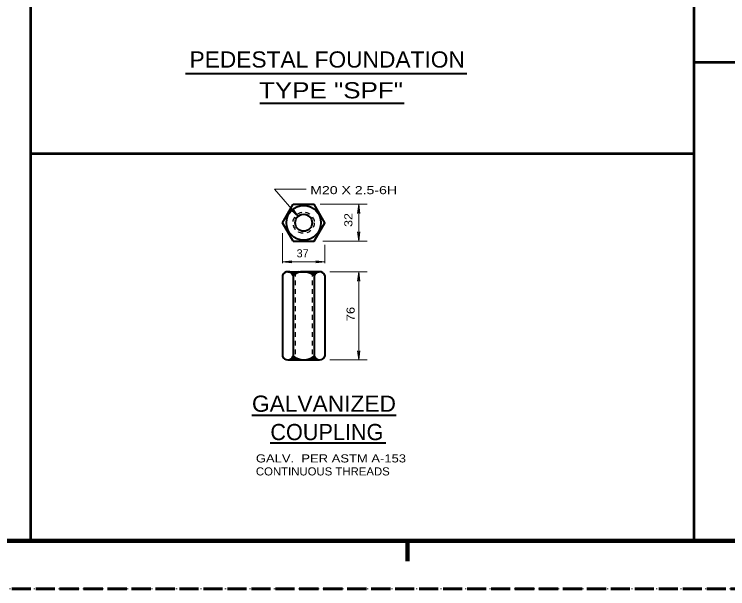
# Model space of a CAD drawing. Extents: x 312583 to 312854, y 144419 to 144597.
# Drawn here: x 312690.4 to 312757.4, y 144418.6 to 144472.5 of the extents above; entities that cross this region are included whole.
import ezdxf
from ezdxf.enums import TextEntityAlignment as Align

# ---------------------------------------------------------------- set-up
doc = ezdxf.new("R2010")
doc.units = 0
doc.header["$LTSCALE"] = 0.3
for name, pattern in [('DOTTED', [1.5, 0.3, -1.2]), ('LONG_DASHED', [7.5, 6, -1.5]), ('SHORT_DASHED', [2.7, 1.5, -1.2])]:
    doc.linetypes.add(name, pattern=pattern)
for name, color, linetype, lineweight in [('1', 7, 'Continuous', 25), ('2', 7, 'Continuous', 13), ('62', 7, 'DOTTED', 13), ('63', 7, 'LONG_DASHED', 60)]:
    doc.layers.add(name, color=color, linetype=linetype, lineweight=lineweight)

msp = doc.modelspace()

# ---------------------------------------------------------------- linework, layer by layer
at = {"layer": '1', "lineweight": 53}
for p, q in [((312691.9772, 144423.0846), (312691.9772, 144585.0846)), ((312754.2862, 144423.0846), (312754.2862, 144585.0846)), ((312849, 144468), (312754.2862, 144468)), ((312754.2862, 144459.4229), (312691.9772, 144459.4229))]:
    msp.add_line(p, q, dxfattribs=at)
at = {"layer": '1', "lineweight": 40}
for p, q in [((312715.6179, 144452.9535), (312716.6145, 144454.6785)), ((312716.6145, 144454.6785), (312718.6079, 144454.6785)), ((312716.6145, 144451.2285), (312715.6179, 144452.9535)), ((312716.6145, 144451.2285), (312718.6079, 144451.2285)), ((312715.6179, 144448.0009), (312715.6179, 144440.4109)), ((312716.1162, 144448.3459), (312719.0602, 144448.3459)), ((312716.6145, 144448.0009), (312716.6145, 144440.4109)), ((312718.6002, 144448.0009), (312718.6002, 144440.4109)), ((312719.6045, 144448.0009), (312719.6045, 144440.4109)), ((312716.1162, 144440.0659), (312719.0602, 144440.0659)), ((312716.1162, 144440.0659), (312719.0602, 144440.0659))]:
    msp.add_line(p, q, dxfattribs=at)
at = {"layer": '1', "linetype": 'SHORT_DASHED'}
for p, q in [((312716.8139, 144448.3459), (312716.8139, 144440.0659)), ((312718.4085, 144448.3459), (312718.4085, 144440.0659))]:
    msp.add_line(p, q, dxfattribs=at)
at = {"layer": '1', "lineweight": 158}
for p, q in [((312616.5, 144423.0846), (312849, 144423.0846)), ((312727.35, 144421.1646), (312727.35, 144423.0846))]:
    msp.add_line(p, q, dxfattribs=at)
at = {"layer": '1', "lineweight": 40}
for points in [[(312718.6079, 144451.2285), (312719.6045, 144452.9535), (312718.6079, 144454.6785)], [(312716.2695, 144448.3382), (312717.3429, 144448.3459), (312717.1205, 144448.2922), (312716.8675, 144448.1849), (312716.6375, 144448.0315), (312716.5455, 144448.1465), (312716.4459, 144448.2539), (312716.3309, 144448.3229), (312717.1819, 144448.3305), (312716.9825, 144448.2692), (312716.8139, 144448.1772), (312716.6452, 144448.0699), (312716.5839, 144448.1389), (312716.4612, 144448.2615), (312716.3999, 144448.2922), (312717.0669, 144448.3152), (312716.6452, 144448.1005), (312716.4842, 144448.2615), (312716.9672, 144448.2922), (312716.6452, 144448.1312), (312716.5455, 144448.2539), (312716.8905, 144448.2769), (312716.6529, 144448.1619), (312716.5992, 144448.2462), (312716.7602, 144448.2462), (312716.6605, 144448.2002), (312716.6529, 144448.2462), (312716.7219, 144448.2309)], [(312718.9529, 144448.3382), (312717.8795, 144448.3459), (312718.1019, 144448.2922), (312718.3549, 144448.1849), (312718.5849, 144448.0315), (312718.6692, 144448.1465), (312718.7765, 144448.2539), (312718.8915, 144448.3229), (312718.0405, 144448.3305), (312718.2399, 144448.2692), (312718.4085, 144448.1772), (312718.5772, 144448.0699), (312718.6385, 144448.1389), (312718.7612, 144448.2615), (312718.8225, 144448.2922), (312718.1555, 144448.3152), (312718.5772, 144448.1005), (312718.7305, 144448.2615), (312718.2475, 144448.2922), (312718.5772, 144448.1312), (312718.6769, 144448.2539), (312718.3242, 144448.2769), (312718.5695, 144448.1619), (312718.6232, 144448.2462), (312718.4545, 144448.2462), (312718.5619, 144448.2002), (312718.5695, 144448.2462), (312718.5005, 144448.2309)], [(312716.2695, 144440.0812), (312717.3429, 144440.0735), (312717.1205, 144440.1272), (312716.8675, 144440.2345), (312716.6375, 144440.3879), (312716.5455, 144440.2729), (312716.4459, 144440.1655), (312716.3309, 144440.1042), (312717.1819, 144440.0889), (312716.9825, 144440.1502), (312716.8139, 144440.2499), (312716.6452, 144440.3419), (312716.5839, 144440.2729), (312716.4612, 144440.1579), (312716.3999, 144440.1272), (312717.0669, 144440.1042), (312716.6452, 144440.3189), (312716.4842, 144440.1579), (312716.9672, 144440.1272), (312716.6452, 144440.2882), (312716.5455, 144440.1655), (312716.8905, 144440.1425), (312716.6529, 144440.2575), (312716.5992, 144440.1809), (312716.7602, 144440.1732), (312716.6605, 144440.2192), (312716.6529, 144440.1809), (312716.7219, 144440.1885)], [(312718.9529, 144440.0812), (312717.8795, 144440.0735), (312718.1019, 144440.1272), (312718.3549, 144440.2345), (312718.5849, 144440.3879), (312718.6692, 144440.2729), (312718.7765, 144440.1655), (312718.8915, 144440.1042), (312718.0405, 144440.0889), (312718.2399, 144440.1502), (312718.4085, 144440.2499), (312718.5772, 144440.3419), (312718.6385, 144440.2729), (312718.7612, 144440.1579), (312718.8225, 144440.1272), (312718.1555, 144440.1042), (312718.5772, 144440.3189), (312718.7305, 144440.1579), (312718.2475, 144440.1272), (312718.5772, 144440.2882), (312718.6769, 144440.1655), (312718.3242, 144440.1425), (312718.5695, 144440.2575), (312718.6232, 144440.1809), (312718.4545, 144440.1732), (312718.5619, 144440.2192), (312718.5695, 144440.1809), (312718.5005, 144440.1885)]]:
    msp.add_lwpolyline(points, dxfattribs=at)
for radius in [1.6267, 0.7949]:
    msp.add_circle((312717.6103, 144452.9514), radius, dxfattribs=at)
at = {"layer": '1', "linetype": 'SHORT_DASHED'}
msp.add_circle((312717.6103, 144452.9514), 0.9936, dxfattribs=at)
at = {"layer": '1', "lineweight": 40}
for centre, radius, start, end in [((312716.1172, 144447.8161), 0.5342, 20.74148, 159.25852), ((312717.6103, 144446.747), 1.6033, 51.70372, 128.29627), ((312719.1035, 144447.8161), 0.5342, 20.74148, 159.25852), ((312716.1172, 144440.6045), 0.5342, 200.74148, 339.25852), ((312717.6103, 144441.6736), 1.6033, 231.70372, 308.29627), ((312719.1035, 144440.6045), 0.5342, 200.74148, 339.25852)]:
    msp.add_arc(centre, radius, start, end, dxfattribs=at)
at = {"layer": '2', "lineweight": 40}
for p, q in [((312706.5259, 144466.9764), (312732.9375, 144466.9764)), ((312713.496, 144464.1647), (312727.0538, 144464.1647)), ((312712.7416, 144434.8752), (312726.2834, 144434.8752)), ((312714.4658, 144432.2839), (312725.3136, 144432.2839))]:
    msp.add_line(p, q, dxfattribs=at)
at = {"layer": '2'}
for p, q in [((312719.1445, 144454.6785), (312723.5605, 144454.6785)), ((312722.7785, 144454.6785), (312722.6712, 144453.8122)), ((312722.7785, 144451.2285), (312722.7785, 144454.6785)), ((312722.7785, 144454.6785), (312722.8859, 144453.8122)), ((312716.4459, 144454.1342), (312716.7065, 144453.9962)), ((312717.0899, 144453.5515), (312716.4459, 144454.1342)), ((312716.6069, 144454.2799), (312716.7065, 144453.9962)), ((312717.0899, 144453.5515), (312716.6069, 144454.2799)), ((312722.6712, 144453.8122), (312722.7785, 144454.0882)), ((312722.8859, 144453.8122), (312722.7785, 144454.0882)), ((312715.6179, 144451.9645), (312715.6179, 144449.1509)), ((312722.6712, 144452.0949), (312722.7785, 144451.8189)), ((312722.7785, 144451.2285), (312722.6712, 144452.0949)), ((312722.8859, 144452.0949), (312722.7785, 144451.8189)), ((312722.7785, 144451.2285), (312722.8859, 144452.0949)), ((312719.4052, 144451.2285), (312723.5605, 144451.2285)), ((312719.6045, 144450.8759), (312719.6045, 144449.1585)), ((312715.6179, 144449.2812), (312716.4842, 144449.3885)), ((312715.6179, 144449.2812), (312719.6045, 144449.2812)), ((312715.6179, 144449.2812), (312716.4842, 144449.1739)), ((312716.4842, 144449.3885), (312716.2082, 144449.2812)), ((312716.4842, 144449.1739), (312716.2082, 144449.2812)), ((312718.7382, 144449.3885), (312719.0142, 144449.2812)), ((312719.6045, 144449.2812), (312718.7382, 144449.3885)), ((312718.7382, 144449.1739), (312719.0142, 144449.2812)), ((312719.6045, 144449.2812), (312718.7382, 144449.1739)), ((312720.0799, 144448.3459), (312723.5605, 144448.3459)), ((312722.7785, 144448.3459), (312722.6712, 144447.4795)), ((312722.6712, 144447.4795), (312722.7785, 144447.7555)), ((312722.7785, 144440.0659), (312722.7785, 144448.3459)), ((312722.7785, 144448.3459), (312722.8859, 144447.4795)), ((312722.8859, 144447.4795), (312722.7785, 144447.7555)), ((312722.6712, 144440.9322), (312722.7785, 144440.6562)), ((312722.7785, 144440.0659), (312722.6712, 144440.9322)), ((312722.8859, 144440.9322), (312722.7785, 144440.6562)), ((312722.7785, 144440.0659), (312722.8859, 144440.9322)), ((312720.0799, 144440.0659), (312723.5605, 144440.0659))]:
    msp.add_line(p, q, dxfattribs=at)
msp.add_lwpolyline([(312717.8489, 144456.1122), (312714.8742, 144456.1122), (312717.0899, 144453.5515)], dxfattribs=at)
at = {"layer": '62'}
msp.add_lwpolyline([(312601.2, 144418.5846), (312853.5, 144418.5846), (312853.5, 144596.7846)], dxfattribs=at)
at = {"layer": '63'}
msp.add_line((312851.75, 144418.5846), (312583.526, 144418.5846), dxfattribs=at)

# ---------------------------------------------------------------- texts
at = {"layer": '2'}
for s, width, p in [('PEDESTAL FOUNDATION', 1.05, (312719.8188, 144467.5204)), ('TYPE "SPF"', 1.2, (312720.1751, 144464.6282)), ('GALVANIZED', 1.05, (312719.515, 144435.2007))]:
    msp.add_text(s, height=1.52, dxfattribs=dict(at, width=width)).set_placement(p, align=Align.CENTER)
for s, width, p in [('M20 X 2.5-6H', 1.3, (312718.2265, 144455.6303)), ('GALV.  PER ASTM A-153', 1.2, (312713.123, 144430.4423)), ('CONTINUOUS THREADS', 1.05, (312713.123, 144429.2223))]:
    msp.add_text(s, height=0.76, dxfattribs=dict(at, width=width)).set_placement(p)
for s, width, p in [('32 ', 1.15, (312722.1868, 144452.5583)), ('76 ', 1.2, (312722.396, 144443.6954))]:
    msp.add_text(s, height=0.76, rotation=90, dxfattribs=dict(at, width=width)).set_placement(p)
msp.add_text('37', height=0.76, dxfattribs=at).set_placement((312716.9475, 144449.7002))
msp.add_text('COUPLING', height=1.52, dxfattribs=at).set_placement((312719.7906, 144432.5375), align=Align.CENTER)

doc.saveas('drawing.dxf')
